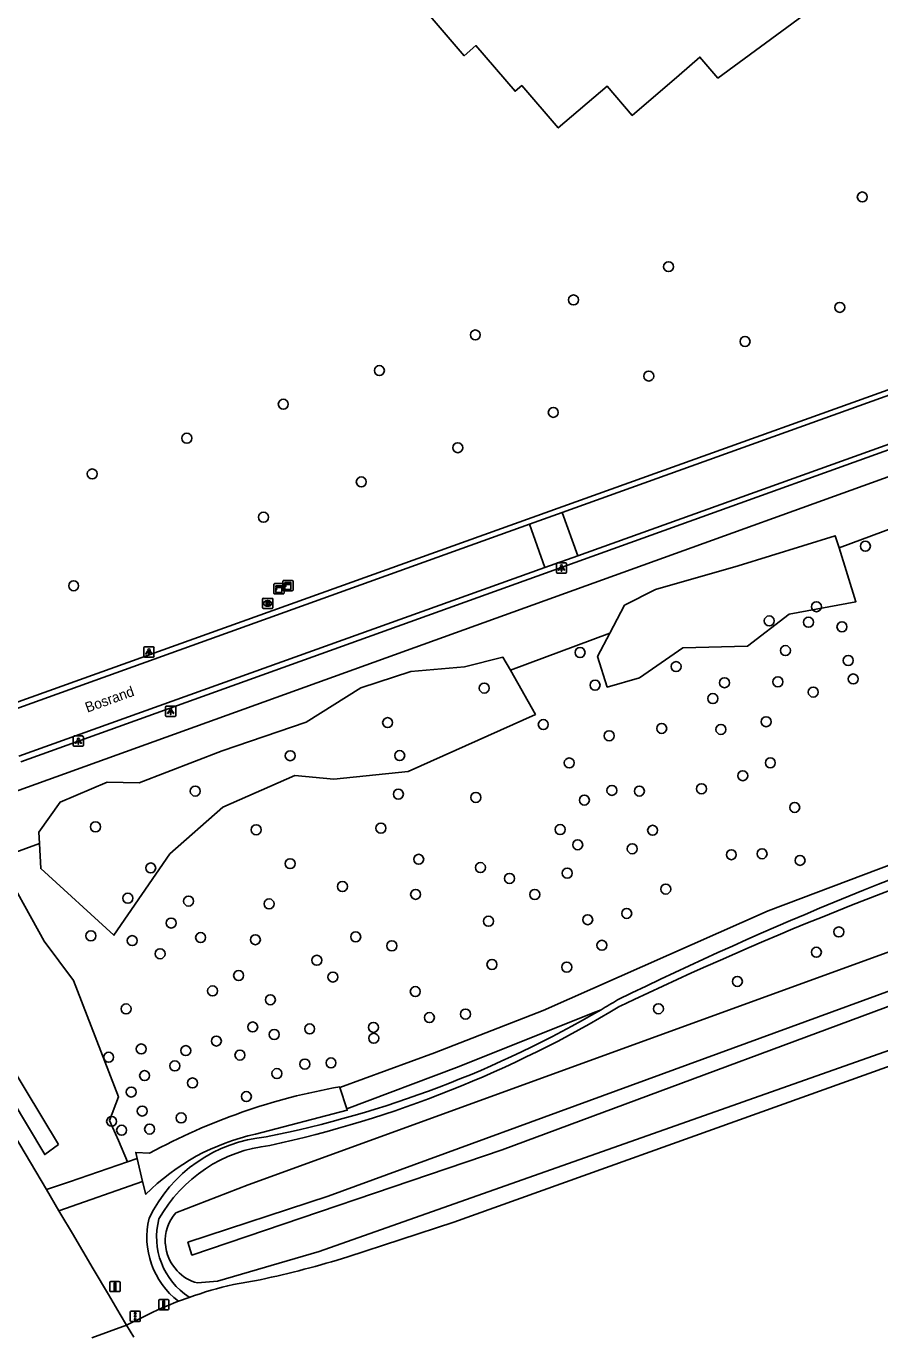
# Model space of a CAD drawing. Extents: x 156664 to 157568, y 383571 to 384421.
# Drawn here: x 156803.6 to 156887.2, y 383631.2 to 383759.7 of the extents above; entities that cross this region are included whole.
import ezdxf

# ---------------------------------------------------------------- set-up
doc = ezdxf.new("R2010")
doc.units = 0
for name, color, linetype in [('IMGEO_Boom', 7, 'Continuous'), ('IMGEO_Brandkraan', 7, 'Continuous'), ('IMGEO_Fietspad_gesloten', 7, 'Continuous'), ('IMGEO_Groenvoorziening', 7, 'Continuous'), ('IMGEO_Kast', 7, 'Continuous'), ('IMGEO_Lichtpunt', 7, 'Continuous'), ('IMGEO_Loofbos', 7, 'Continuous'), ('IMGEO_Openbare_ruimte_label', 7, 'Continuous'), ('IMGEO_OVBaan_gesloten', 7, 'Continuous'), ('IMGEO_Pand_vergunning_verleend', 7, 'Continuous'), ('IMGEO_Rijbaan_lokaal_halfverhard', 7, 'Continuous'), ('IMGEO_Rijbaan_lokaal_open', 7, 'Continuous'), ('IMGEO_Verkeersbordpaal', 7, 'Continuous'), ('IMGEO_Verkeersregelinstallatiepaal', 7, 'Continuous'), ('IMGEO_Voetpad_onverhard', 7, 'Continuous'), ('IMGEO_Waterloop', 7, 'Continuous')]:
    doc.layers.add(name, color=color, linetype=linetype)

msp = doc.modelspace()

# ---------------------------------------------------------------- linework, layer by layer
at = {"layer": 'IMGEO_Boom'}
for centre in [(156885.52, 383742.94), (156866.54, 383736.11), (156857.23, 383732.85), (156883.31, 383732.12), (156847.61, 383729.42), (156874.03, 383728.78), (156838.21, 383725.93), (156864.6, 383725.39), (156828.8, 383722.63), (156855.25, 383721.83), (156819.35, 383719.3), (156845.89, 383718.37), (156810.08, 383715.8), (156836.44, 383715.02), (156826.86, 383711.56), (156885.82, 383708.72), (156808.26, 383704.84), (156881.03, 383702.79), (156876.4, 383701.4), (156880.25, 383701.27), (156883.53, 383700.82), (156857.87, 383698.3), (156877.99, 383698.49), (156867.28, 383696.92), (156884.14, 383697.52), (156859.34, 383695.1), (156872.02, 383695.34), (156877.25, 383695.43), (156884.63, 383695.71), (156848.48, 383694.81), (156870.88, 383693.79), (156880.71, 383694.42), (156839.02, 383691.43), (156854.27, 383691.24), (156876.1, 383691.52), (156860.72, 383690.14), (156865.87, 383690.86), (156871.67, 383690.76), (156829.48, 383688.19), (156840.2, 383688.2), (156856.81, 383687.48), (156876.51, 383687.49), (156873.81, 383686.23), (156820.17, 383684.72), (156860.99, 383684.79), (156863.68, 383684.72), (156869.77, 383684.95), (156840.07, 383684.42), (156847.66, 383684.1), (156858.29, 383683.84), (156878.9, 383683.12), (156810.4, 383681.22), (156826.14, 383680.93), (156838.36, 383681.09), (156855.92, 383680.95), (156864.98, 383680.88), (156857.64, 383679.46), (156862.98, 383679.07), (156872.69, 383678.49), (156875.7, 383678.58), (156815.81, 383677.19), (156829.47, 383677.61), (156842.06, 383678.04), (156848.11, 383677.23), (156879.42, 383677.93), (156850.96, 383676.16), (156856.61, 383676.68), (156834.59, 383675.37), (156841.76, 383674.6), (156853.43, 383674.59), (156866.27, 383675.12), (156813.57, 383674.22), (156819.52, 383673.94), (156827.41, 383673.67), (156848.9, 383671.97), (156858.62, 383672.12), (156862.44, 383672.73), (156817.81, 383671.79), (156883.22, 383670.92), (156809.95, 383670.54), (156814, 383670.07), (156820.7, 383670.37), (156826.06, 383670.16), (156835.89, 383670.44), (156839.43, 383669.56), (156860.01, 383669.61), (156816.73, 383668.78), (156832.08, 383668.14), (156881.02, 383668.93), (156849.24, 383667.73), (156856.57, 383667.47), (156824.42, 383666.65), (156833.66, 383666.5), (156873.28, 383666.07), (156821.87, 383665.14), (156827.53, 383664.27), (156841.73, 383665.08), (156813.4, 383663.38), (156846.65, 383662.87), (156865.55, 383663.39), (156825.8, 383661.61), (156843.11, 383662.53), (156827.91, 383660.87), (156831.38, 383661.42), (156837.63, 383661.57), (156837.66, 383660.5), (156814.88, 383659.45), (156819.24, 383659.29), (156822.24, 383660.23), (156811.69, 383658.64), (156818.17, 383657.79), (156824.55, 383658.85), (156830.91, 383657.97), (156833.47, 383658.09), (156815.21, 383656.84), (156828.17, 383657.04), (156813.9, 383655.23), (156819.9, 383656.12), (156825.18, 383654.79), (156814.98, 383653.37), (156818.79, 383652.7), (156811.98, 383652.36), (156812.96, 383651.49), (156815.7, 383651.6)]:
    msp.add_circle(centre, 0.489, dxfattribs=at)
at = {"layer": 'IMGEO_Brandkraan'}
for p, q in [((156826.77, 383702.69), (156826.77, 383703.54)), ((156826.85, 383703.61), (156827.7, 383703.61)), ((156827.26, 383703.39), (156827.28, 383703.39)), ((156827.77, 383703.54), (156827.77, 383702.69)), ((156827.7, 383702.61), (156826.85, 383702.61)), ((156827.28, 383702.83), (156827.26, 383702.83))]:
    msp.add_line(p, q, dxfattribs=at)
for points in [[(156826.77, 383702.69), (156826.77, 383703.54)], [(156826.85, 383703.61), (156827.7, 383703.61)], [(156827.12, 383703.31), (156827.12, 383702.91), (156827.33, 383702.91)], [(156827.35, 383703.31), (156827.12, 383703.31)], [(156827.3, 383703.23), (156827.24, 383703.23), (156827.24, 383703.15)], [(156827.77, 383703.54), (156827.77, 383702.69)], [(156827.7, 383702.61), (156826.85, 383702.61)], [(156827.24, 383703.15), (156827.3, 383703.15)], [(156827.31, 383703.08), (156827.24, 383703.08), (156827.24, 383703)], [(156827.24, 383703), (156827.31, 383703)]]:
    msp.add_lwpolyline(points, dxfattribs=at)
for centre, radius, start, end in [((156826.85, 383703.54), 0.0765, 91.552, 178.448), ((156826.85, 383703.54), 0.0765, 91.552, 178.448), ((156827.3, 383703.19), 0.0379, 267.8285, 90.9355), ((156827.35, 383703.17), 0.145, 59.4692, 91.5367), ((156827.38, 383703.21), 0.0922, 285.5137, 58.1501), ((156827.7, 383703.54), 0.0765, 1.552, 88.448), ((156827.7, 383703.54), 0.0765, 1.552, 88.448), ((156826.85, 383702.69), 0.0765, 181.552, 268.448), ((156826.85, 383702.69), 0.0765, 181.552, 268.448), ((156827.31, 383703.04), 0.0404, 269.8759, 90.5077), ((156827.34, 383703.16), 0.251, 268.6676, 293.5347), ((156827.38, 383703.02), 0.105, 301.3115, 78.989), ((156827.7, 383702.69), 0.0765, 271.552, 358.448), ((156827.7, 383702.69), 0.0765, 271.552, 358.448)]:
    msp.add_arc(centre, radius, start, end, dxfattribs=at)
for centre, major_axis, ratio, start_param, end_param in [((156827.26, 383703.11), (-0.387, 0.002), 0.722429, 4.712389, 7.853982), ((156827.28, 383703.11), (-0.39, 0.002), 0.717154, 1.570796, 4.712389)]:
    msp.add_ellipse(centre, major_axis=major_axis, ratio=ratio, start_param=start_param, end_param=end_param, dxfattribs=at)
at = {"layer": 'IMGEO_Fietspad_gesloten'}
for points in [[(156835.12, 383639.07), (156845.49, 383642.47), (156918.07, 383668.49), (156979.95, 383690.48), (157000, 383697.71), (157004.59, 383699.36), (157043.51, 383713.39), (157106.61, 383736.03), (157124.32, 383742.33), (157131.66, 383745.02), (157135.74, 383746.91), (157137.6, 383747.87), (157148.48, 383753.68), (157148.48, 383753.68)], [(156823.91, 383636.37), (156826.53, 383636.83)], [(156819.56, 383635.11), (156818.53, 383634.73)], [(156815.22, 383633.26), (156813.44, 383632.4)]]:
    msp.add_lwpolyline(points, dxfattribs=at)
for centre, radius, start, end in [((156804.38, 383739.38), 104.91, 282.1879, 287.0419), ((156832.52, 383598.61), 38.73, 102.8378, 109.5429), ((156831.64, 383600.59), 36.57, 111.0018, 116.6857)]:
    msp.add_arc(centre, radius, start, end, dxfattribs=at)
at = {"layer": 'IMGEO_Groenvoorziening'}
for points in [[(156818.26, 383643.4), (156825.36, 383646.15), (157071.88, 383735.81), (157097.58, 383744.47), (157105.66, 383748.02), (157115.13, 383751.65), (157124.63, 383755.12), (157127.94, 383756.46), (157131.64, 383758.9), (157143.74, 383766.75), (157148.73, 383769.94)], [(157154.27, 383759.36), (157142.79, 383754.17), (157133.56, 383749.42), (157126.9, 383746.55), (157115.73, 383742.47), (157107.79, 383738.98), (157094.28, 383733.56), (156957.48, 383683.79), (156832.31, 383639.6), (156822.36, 383636.71), (156820.4, 383636.53)], [(156806.77, 383650.1), (156805.42, 383649.11), (156790.61, 383673.87), (156791.96, 383674.64), (156806.77, 383650.1)], [(156835.02, 383653.6), (156835.07, 383653.45), (156826.09, 383651.1)], [(156813.53, 383648.38), (156807.84, 383646.44), (156805.59, 383645.67)], [(156815.02, 383646.48), (156814.49, 383648.71)], [(156806.82, 383643.6), (156815.02, 383646.48)], [(156815.32, 383645.2), (156815.02, 383646.48)]]:
    msp.add_lwpolyline(points, dxfattribs=at)
for centre, radius, start, end in [((156830.73, 383629.86), 21.75, 102.3385, 135.1363), ((156821.48, 383640.63), 4.25, 139.3778, 183.7297), ((156821.47, 383640.63), 4.23, 183.6665, 223.5081), ((156821.48, 383640.63), 4.25, 223.4176, 255.2041)]:
    msp.add_arc(centre, radius, start, end, dxfattribs=at)
at = {"layer": 'IMGEO_Kast'}
for p, q in [((156827.87, 383704.12), (156827.87, 383704.96)), ((156827.87, 383704.96), (156827.87, 383704.12)), ((156827.94, 383705.05), (156828.79, 383705.05)), ((156828.79, 383705.05), (156827.94, 383705.05)), ((156828.75, 383704.43), (156828.75, 383705.27)), ((156828.75, 383705.27), (156828.75, 383704.43)), ((156828.83, 383705.36), (156829.67, 383705.36)), ((156829.67, 383705.36), (156828.83, 383705.36)), ((156828.87, 383704.97), (156828.87, 383704.13)), ((156828.87, 383704.13), (156828.87, 383704.97)), ((156829.75, 383705.28), (156829.75, 383704.44)), ((156829.75, 383704.44), (156829.75, 383705.28)), ((156828.8, 383704.05), (156827.95, 383704.05)), ((156827.95, 383704.05), (156828.8, 383704.05)), ((156829.68, 383704.36), (156828.84, 383704.36)), ((156828.84, 383704.36), (156829.68, 383704.36))]:
    msp.add_line(p, q, dxfattribs=at)
for points in [[(156828.07, 383704.84), (156828.67, 383704.84), (156828.67, 383704.75), (156828.07, 383704.75), (156828.07, 383704.84)], [(156828.07, 383704.66), (156828.67, 383704.66), (156828.67, 383704.17), (156828.07, 383704.17), (156828.07, 383704.66)], [(156828.95, 383705.15), (156829.55, 383705.15), (156829.55, 383705.06), (156828.95, 383705.06), (156828.95, 383705.15)], [(156828.95, 383704.97), (156829.55, 383704.97), (156829.55, 383704.48), (156828.95, 383704.48), (156828.95, 383704.97)]]:
    msp.add_lwpolyline(points, dxfattribs=at)
for centre in [(156828.15, 383704.51), (156829.03, 383704.82)]:
    msp.add_circle(centre, 0.0377, dxfattribs=at)
for centre, start, end in [((156827.95, 383704.97), 92.4484, 184.2845), ((156827.95, 383704.97), 92.4484, 184.2845), ((156828.83, 383705.28), 92.4484, 184.2845), ((156828.83, 383705.28), 92.4484, 184.2845), ((156828.79, 383704.97), 2.4484, 94.2845), ((156828.79, 383704.97), 2.4484, 94.2845), ((156829.68, 383705.28), 2.4484, 94.2845), ((156829.68, 383705.28), 2.4484, 94.2845), ((156827.95, 383704.12), 182.4484, 274.2845), ((156827.95, 383704.12), 182.4484, 274.2845), ((156828.83, 383704.44), 182.4484, 274.2845), ((156828.83, 383704.44), 182.4484, 274.2845), ((156828.79, 383704.12), 272.4484, 4.2845), ((156828.79, 383704.12), 272.4484, 4.2845), ((156829.68, 383704.44), 272.4484, 4.2845), ((156829.68, 383704.44), 272.4484, 4.2845)]:
    msp.add_arc(centre, 0.0779, start, end, dxfattribs=at)
at = {"layer": 'IMGEO_Lichtpunt'}
for p, q in [((156856.45, 383707.08), (156855.65, 383707.08)), ((156856.45, 383707.08), (156855.65, 383707.08)), ((156855.55, 383706.99), (156855.55, 383706.18)), ((156855.55, 383706.99), (156855.55, 383706.18)), ((156855.65, 383706.09), (156856.45, 383706.09)), ((156855.65, 383706.09), (156856.45, 383706.09)), ((156856.55, 383706.18), (156856.55, 383706.99)), ((156856.55, 383706.18), (156856.55, 383706.99)), ((156815.14, 383698.76), (156815.14, 383697.95)), ((156815.14, 383698.76), (156815.14, 383697.95)), ((156816.04, 383698.85), (156815.23, 383698.85)), ((156816.04, 383698.85), (156815.23, 383698.85)), ((156816.13, 383697.95), (156816.13, 383698.76)), ((156816.13, 383697.95), (156816.13, 383698.76)), ((156815.23, 383697.85), (156816.04, 383697.85)), ((156815.23, 383697.85), (156816.04, 383697.85)), ((156817.26, 383692.95), (156817.26, 383692.14)), ((156817.26, 383692.95), (156817.26, 383692.14)), ((156818.17, 383693.04), (156817.36, 383693.04)), ((156818.17, 383693.04), (156817.36, 383693.04)), ((156818.26, 383692.14), (156818.26, 383692.95)), ((156818.26, 383692.14), (156818.26, 383692.95)), ((156817.36, 383692.04), (156818.17, 383692.04)), ((156817.36, 383692.04), (156818.17, 383692.04)), ((156808.22, 383690.02), (156808.22, 383689.22)), ((156808.22, 383690.02), (156808.22, 383689.22)), ((156809.12, 383690.12), (156808.31, 383690.12)), ((156809.12, 383690.12), (156808.31, 383690.12)), ((156808.31, 383689.12), (156809.12, 383689.12)), ((156808.31, 383689.12), (156809.12, 383689.12)), ((156809.22, 383689.22), (156809.22, 383690.02)), ((156809.22, 383689.22), (156809.22, 383690.02))]:
    msp.add_line(p, q, dxfattribs=at)
for points in [[(156855.93, 383706.65), (156855.96, 383706.62), (156855.78, 383706.36), (156855.74, 383706.39), (156855.93, 383706.65)], [(156856.03, 383706.6), (156856.08, 383706.6), (156856.08, 383706.28), (156856.03, 383706.28), (156856.03, 383706.6)], [(156856.14, 383706.62), (156856.18, 383706.65), (156856.36, 383706.39), (156856.32, 383706.36), (156856.14, 383706.62)], [(156815.51, 383698.42), (156815.55, 383698.39), (156815.36, 383698.13), (156815.32, 383698.16), (156815.51, 383698.42)], [(156815.61, 383698.37), (156815.66, 383698.37), (156815.66, 383698.05), (156815.61, 383698.05), (156815.61, 383698.37)], [(156815.72, 383698.39), (156815.76, 383698.42), (156815.95, 383698.16), (156815.91, 383698.13), (156815.72, 383698.39)], [(156817.64, 383692.61), (156817.68, 383692.58), (156817.49, 383692.32), (156817.45, 383692.35), (156817.64, 383692.61)], [(156817.74, 383692.56), (156817.79, 383692.56), (156817.79, 383692.24), (156817.74, 383692.24), (156817.74, 383692.56)], [(156817.85, 383692.58), (156817.89, 383692.61), (156818.07, 383692.35), (156818.04, 383692.32), (156817.85, 383692.58)], [(156808.59, 383689.69), (156808.63, 383689.66), (156808.44, 383689.4), (156808.41, 383689.43), (156808.59, 383689.69)], [(156808.69, 383689.64), (156808.74, 383689.64), (156808.74, 383689.32), (156808.69, 383689.32), (156808.69, 383689.64)], [(156808.8, 383689.66), (156808.84, 383689.69), (156809.03, 383689.42), (156808.99, 383689.4), (156808.8, 383689.66)]]:
    msp.add_lwpolyline(points, dxfattribs=at)
for centre in [(156856.05, 383706.79), (156815.64, 383698.55), (156817.76, 383692.74), (156808.72, 383689.82)]:
    msp.add_circle(centre, 0.0994, dxfattribs=at)
for centre, start, end in [((156855.65, 383706.99), 90, 180), ((156855.65, 383706.99), 90, 180), ((156856.45, 383706.99), 0, 90), ((156856.45, 383706.99), 0, 90), ((156855.65, 383706.18), 180, 270), ((156855.65, 383706.18), 180, 270), ((156856.45, 383706.18), 270, 0), ((156856.45, 383706.18), 270, 360), ((156815.23, 383698.76), 90, 180), ((156815.23, 383698.76), 90, 180), ((156816.04, 383698.76), 0, 90), ((156816.04, 383698.76), 0, 90), ((156815.23, 383697.95), 180, 270), ((156815.23, 383697.95), 180, 270), ((156816.04, 383697.95), 270, 0), ((156816.04, 383697.95), 270, 360), ((156817.36, 383692.95), 90, 180), ((156817.36, 383692.95), 90, 180), ((156818.17, 383692.95), 0, 90), ((156818.17, 383692.95), 0, 90), ((156817.36, 383692.14), 180, 270), ((156817.36, 383692.14), 180, 270), ((156818.17, 383692.14), 270, 0), ((156818.17, 383692.14), 270, 360), ((156808.31, 383690.02), 90, 180), ((156808.31, 383690.02), 90, 180), ((156808.31, 383689.22), 180, 270), ((156808.31, 383689.22), 180, 270), ((156809.12, 383690.02), 0, 90), ((156809.12, 383690.02), 0, 90), ((156809.12, 383689.22), 270, 0), ((156809.12, 383689.22), 270, 360)]:
    msp.add_arc(centre, 0.0946, start, end, dxfattribs=at)
at = {"layer": 'IMGEO_Loofbos'}
for points in [[(157051.73, 383755.8), (157034.82, 383750.5), (157002.63, 383740.41), (156953.89, 383739.27), (156797.72, 383682.96)], [(156993.19, 383715.51), (156989.91, 383714.12), (156983.73, 383711.79), (156967.54, 383706.76), (156960.58, 383704.39), (156947.11, 383698.61), (156925.49, 383690.09), (156916.78, 383686.98), (156907.11, 383684.23), (156898.18, 383681.26), (156876.31, 383672.99), (156854.26, 383663.23), (156843.61, 383659.07), (156834.34, 383655.68)], [(156883.24, 383708.55), (156898.22, 383714.12)], [(156883.24, 383708.55), (156882.87, 383709.74), (156873.35, 383706.79), (156865.26, 383704.48), (156862.21, 383702.93), (156860.79, 383700.2)], [(156860.79, 383700.2), (156859.59, 383697.9), (156860.54, 383694.92), (156863.69, 383695.83), (156867.93, 383698.75), (156874.26, 383698.93), (156878.37, 383702.06), (156884.89, 383703.27), (156883.24, 383708.55)], [(156851.04, 383696.58), (156860.79, 383700.2)], [(156851.04, 383696.58), (156850.32, 383697.84), (156846.56, 383696.91), (156841.3, 383696.45), (156836.39, 383694.83), (156831.03, 383691.49), (156822.82, 383688.66), (156814.68, 383685.53), (156811.54, 383685.61), (156806.93, 383683.63), (156804.85, 383680.71), (156804.91, 383679.59)], [(156804.91, 383679.59), (156805.03, 383677.12), (156812.2, 383670.59), (156817.68, 383678.57), (156822.87, 383683.13), (156829.93, 383686.24), (156833.74, 383685.89), (156841.04, 383686.64), (156853.49, 383692.24), (156851.04, 383696.58)], [(156800.87, 383678.13), (156804.91, 383679.59)], [(156813.53, 383648.38), (156812.64, 383650.48), (156811.77, 383652.44), (156812.65, 383654.76), (156808.25, 383666.15), (156805.38, 383670), (156800.87, 383678.13)], [(156835.02, 383653.6), (156845.75, 383657.65), (156859.42, 383663.08), (156859.94, 383663.3)], [(156834.32, 383655.73), (156834.34, 383655.68)], [(156834.34, 383655.68), (156835.02, 383653.6)], [(156814.49, 383648.71), (156814.35, 383649.31), (156815.7, 383649.23)], [(156814.49, 383648.71), (156813.53, 383648.38)]]:
    msp.add_lwpolyline(points, dxfattribs=at)
msp.add_arc((156844.79, 383595.89), 60.76, 99.9156, 118.5987, dxfattribs=at)
at = {"layer": 'IMGEO_OVBaan_gesloten'}
for points in [[(156805.59, 383645.67), (156789.05, 383673.56)], [(156806.82, 383643.6), (156805.59, 383645.67)], [(156813.44, 383632.4), (156812.82, 383633.44), (156811.67, 383635.38), (156810.18, 383637.9), (156808.14, 383641.37), (156807, 383643.26), (156806.82, 383643.6)], [(156813.44, 383632.4), (156810.03, 383631.15)], [(156814.15, 383631.2), (156813.44, 383632.4)]]:
    msp.add_lwpolyline(points, dxfattribs=at)
at = {"layer": 'IMGEO_Pand_vergunning_verleend'}
msp.add_lwpolyline([(156879.73, 383760.73), (156871.37, 383754.59), (156869.62, 383756.64), (156867.58, 383754.88), (156862.98, 383750.93), (156860.51, 383753.81), (156855.74, 383749.71), (156852.16, 383753.86), (156851.51, 383753.3), (156847.67, 383757.77), (156846.52, 383756.78), (156842.21, 383761.79)], dxfattribs=at)
at = {"layer": 'IMGEO_Rijbaan_lokaal_halfverhard'}
for points in [[(156801.08, 383692.85), (156953.88, 383747.66)], [(156803.07, 383687.59), (156954.38, 383742)]]:
    msp.add_lwpolyline(points, dxfattribs=at)
at = {"layer": 'IMGEO_Rijbaan_lokaal_open'}
for points in [[(156856.12, 383712.02), (156953.95, 383747.18)], [(156954.25, 383742.47), (156857.65, 383707.79)], [(156852.93, 383710.88), (156856.12, 383712.02)], [(156857.65, 383707.79), (156856.12, 383712.02)], [(156801.24, 383692.3), (156852.93, 383710.88)], [(156852.93, 383710.88), (156854.42, 383706.63)], [(156857.65, 383707.79), (156854.42, 383706.63)], [(156854.42, 383706.63), (156802.88, 383688.13)]]:
    msp.add_lwpolyline(points, dxfattribs=at)
at = {"layer": 'IMGEO_Verkeersbordpaal'}
for p, q in [((156811.81, 383635.77), (156811.81, 383636.57)), ((156811.81, 383636.57), (156811.81, 383635.77)), ((156811.91, 383636.67), (156812.7, 383636.67)), ((156812.7, 383636.67), (156811.91, 383636.67)), ((156812.8, 383636.57), (156812.8, 383635.77)), ((156812.8, 383635.77), (156812.8, 383636.57)), ((156812.7, 383635.67), (156811.91, 383635.67)), ((156811.91, 383635.67), (156812.7, 383635.67)), ((156816.6, 383633.99), (156816.6, 383634.79)), ((156816.6, 383634.79), (156816.6, 383633.99)), ((156816.7, 383634.89), (156817.48, 383634.89)), ((156817.48, 383634.89), (156816.7, 383634.89)), ((156817.48, 383633.89), (156816.7, 383633.89)), ((156816.7, 383633.89), (156817.48, 383633.89)), ((156817.58, 383634.79), (156817.58, 383633.99)), ((156817.58, 383633.99), (156817.58, 383634.79))]:
    msp.add_line(p, q, dxfattribs=at)
for points in [[(156812.23, 383636.54), (156812.38, 383636.54), (156812.38, 383635.79), (156812.23, 383635.79), (156812.23, 383636.54)], [(156817.01, 383634.77), (156817.17, 383634.77), (156817.17, 383634.02), (156817.01, 383634.02), (156817.01, 383634.77)]]:
    msp.add_lwpolyline(points, dxfattribs=at)
for centre, start, end in [((156811.91, 383636.57), 90, 180), ((156811.91, 383636.57), 90, 180), ((156812.7, 383636.57), 0, 90), ((156812.7, 383636.57), 360, 90), ((156811.91, 383635.77), 180, 270), ((156811.91, 383635.77), 180, 270), ((156812.7, 383635.77), 270, 0), ((156812.7, 383635.77), 270, 0), ((156816.7, 383634.79), 90, 180), ((156816.7, 383634.79), 90, 180), ((156816.7, 383633.99), 180, 270), ((156816.7, 383633.99), 180, 270), ((156817.48, 383634.79), 0, 90), ((156817.48, 383634.79), 360, 90), ((156817.48, 383633.99), 270, 0), ((156817.48, 383633.99), 270, 0)]:
    msp.add_arc(centre, 0.1, start, end, dxfattribs=at)
at = {"layer": 'IMGEO_Verkeersregelinstallatiepaal'}
for p, q in [((156813.8, 383632.85), (156813.8, 383633.65)), ((156813.8, 383633.65), (156813.8, 383632.85)), ((156813.9, 383633.75), (156814.69, 383633.75)), ((156814.69, 383633.75), (156813.9, 383633.75)), ((156814.69, 383632.75), (156813.9, 383632.75)), ((156813.9, 383632.75), (156814.69, 383632.75)), ((156814.79, 383633.65), (156814.79, 383632.85)), ((156814.79, 383632.85), (156814.79, 383633.65))]:
    msp.add_line(p, q, dxfattribs=at)
for centre in [(156814.29, 383633.54), (156814.29, 383633.25), (156814.29, 383632.96)]:
    msp.add_circle(centre, 0.085, dxfattribs=at)
for centre, start, end in [((156813.9, 383633.65), 90, 180), ((156813.9, 383633.65), 90, 180), ((156813.9, 383632.85), 180, 270), ((156813.9, 383632.85), 180, 270), ((156814.69, 383633.65), 0, 90), ((156814.69, 383633.65), 360, 90), ((156814.69, 383632.85), 270, 0), ((156814.69, 383632.85), 270, 0)]:
    msp.add_arc(centre, 0.1, start, end, dxfattribs=at)
at = {"layer": 'IMGEO_Voetpad_onverhard'}
for centre, radius, start, end in [((157019.44, 383342.67), 358.26, 108.2009, 116.1516), ((157009.44, 383356.35), 340.92, 107.352, 115.6648), ((156803.59, 383760.04), 112.6, 282.2411, 301.1175), ((156794.89, 383774.19), 128.56, 300.3968, 301.2234), ((156806.3, 383755.11), 106.33, 281.2979, 300.2976), ((156828.49, 383636.63), 14.28, 95.4652, 154.0776), ((156829.01, 383635.9), 14.18, 96.2602, 150.9149), ((156823.35, 383641.02), 7.92, 166.4773, 232.5375), ((156823.45, 383641.01), 7.06, 165.3292, 236.6219)]:
    msp.add_arc(centre, radius, start, end, dxfattribs=at)
at = {"layer": 'IMGEO_Waterloop'}
msp.add_lwpolyline([(157151.24, 383765.15), (157134.53, 383755.88), (157125.61, 383751.99), (157114.52, 383747.76), (157081.61, 383734.6), (157058.85, 383727.28), (157013.96, 383710.31), (156901.06, 383669.84), (156833.19, 383645.04), (156819.46, 383640.51), (156819.84, 383639.25), (156850.23, 383649.57), (156897.55, 383667.14), (156937.77, 383681.3), (156977.08, 383695.66), (157013.16, 383708.73), (157058.33, 383725.73), (157086.26, 383734.97), (157115.55, 383746.16), (157124.7, 383749.59), (157132.7, 383752.79), (157139.78, 383755.88), (157146.43, 383759.19), (157152.69, 383762.39)], dxfattribs=at)

# ---------------------------------------------------------------- texts
at = {"layer": 'IMGEO_Openbare_ruimte_label'}
msp.add_text('Bosrand', height=1, rotation=19.8657, dxfattribs=at).set_placement((156809.6, 383692.4))

doc.saveas('drawing.dxf')
